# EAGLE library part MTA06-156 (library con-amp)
AMP connector
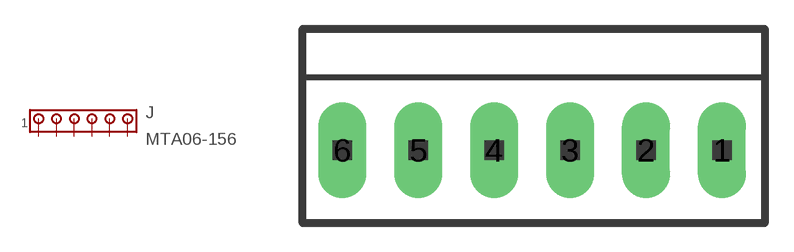
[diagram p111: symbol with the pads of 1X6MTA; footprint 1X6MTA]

Designator prefix J

## MTA06-156 (OC_FARNELL: unknown; OC_NEWARK: unknown)  [1X6MTA]
1  1  pas
2  2  pas
3  3  pas
4  4  pas
5  5  pas
6  6  pas

## Footprint 1X6MTA (pad centres in mm)
AMP MTA connector
drill 1.676 long: 1 9.906,0; 2 5.944,0; 3 1.981,0; 4 -1.981,0; 5 -5.944,0; 6 -9.906,0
